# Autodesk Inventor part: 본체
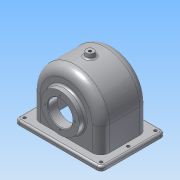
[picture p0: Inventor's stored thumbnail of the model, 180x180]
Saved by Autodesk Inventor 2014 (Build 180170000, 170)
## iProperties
Created: 2015-09
Part Number: 본체
Material: 알루미늄 6061
Document SubType Name: Modeling
Designer: 29
Density: 2.71 g/cm^3
Appearance: 알루미늄 - 평지
Mass: 670.407 g
Surface Area: 886.079 cm^2
Volume: 247.383 cm^3
Author: 29
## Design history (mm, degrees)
sketch "스케치1"
  geometry: L1 (-56, 0)-(-56, -40); L2 (-56, -40)-(56, -40); L3 (56, 0)-(56, -40); A1 r 56 centre (0, 0) between (56, 0) and (-56, 0); 2 further points
  constraints: 6 end point, 2 perpendicular, 2 point on circle, 2 tangent, 1 centre point, 1 coincident, 1 midpoint, 1 vertical, 1 vertical alignment
  dimensions: "d47" = 40 distance from line of L2 point (0, 0); "d48" = 56 radius of A1
extrude "돌출1" new body sketch "스케치1" stored distance "d4" = 77; taper "d5" = 0 deg
feature "쉘4" dims "d50" = 5
sketch "스케치14"
  geometry: L1 (-14, -90.5)-(126, -90.5); L2 (126, -90.5)-(126, 13.5); L3 (126, 13.5)-(-14, 13.5); L4 (-14, 13.5)-(-14, -90.5); L5 (-14, -90.5)-(126, 13.5); L6 (126, -90.5)-(-14, 13.5); 1 further point
  constraints: 12 end point, 2 midpoint, 2 parallel, 1 horizontal, 1 perpendicular
  dimensions: "d51" = 140 distance of L2.end L3.end; "d52" = 104 distance of L3.end L1.start
extrude "돌출10" join sketch "스케치14" distance "d53" = 7; taper "d54" = 0 deg
sketch "스케치15"
  geometry: L1 (5, -72)-(5, -5) reference; L2 (5, -5)-(107, -5) reference; L3 (107, -72)-(5, -72) reference; L4 (107, -5)-(107, -72) reference; 1 further point
extrude "돌출11" cut sketch "스케치15" stored distance "d55" = 7; taper "d56" = 0 deg
sketch "스케치18"
  geometry: L1 (-6, -5.5)-(118, -5.5); L2 (118, -5.5)-(118, 82.5); L3 (118, 82.5)-(-6, 82.5); L4 (-6, 82.5)-(-6, -5.5); L5 (-6, -5.5)-(118, 82.5); L6 (118, -5.5)-(-6, 82.5); C1 r 2.5 at (-6, 82.5); C2 r 2.5 at (-6, 38.5); C3 r 2.5 at (-6, -5.5); 1 further point
  constraints: 12 end point, 3 centre point, 3 midpoint, 2 coincident, 2 parallel, 1 horizontal, 1 perpendicular
  dimensions: "d66" = 124 distance of L2.end L3.end; "d67" = 88 distance of L3.end L1.start; "d68" = 5 diameter of C1; "d69" = 5 diameter of C2; "d70" = 5 diameter of C3
extrude "돌출14" cut sketch "스케치18" stored distance "d71" = 7; taper "d72" = 0 deg
sketch "스케치19"
  geometry: C1 r 31 at (0, 0); A1 r 56 centre (0, 0) between (56, 0) and (-56, 0) reference
  constraints: 1 centre point, 1 coincident
  dimensions: "d73" = 62 diameter of C1
extrude "돌출15" join sketch "스케치19" distance "d74" = 10; taper "d75" = 0 deg
fillet "모깎기2" dims "d76" = 14
fillet "모깎기3" dims "d77" = 9
sketch "스케치20"
  geometry: C1 r 31 at (0, 0) reference; C2 r 20 at (0, 0)
  constraints: 1 centre point, 1 coincident
  dimensions: "d79" = 40 diameter of C2
extrude "돌출16" cut sketch "스케치20" stored distance "d80" = 7; taper "d81" = 0 deg
fillet "모깎기5" dims "d86" = 7
fillet "모깎기6" dims "d87" = 3
node "작업 평면4"
sketch "스케치23"
  geometry: C1 r 28 at (0, 0); 1 further point
  constraints: 1 centre point, 1 coincident
  dimensions: "d92" = 56 diameter of C1
extrude "돌출19" join sketch "스케치23" stored distance "d93" = 16; taper "d94" = 40 deg
sketch "스케치24"
  geometry: C1 r 20 at (0, 0); 1 further point
  constraints: 1 centre point, 1 coincident
  dimensions: "d95" = 40 diameter of C1
extrude "돌출20" cut sketch "스케치24" distance "d96" = 16; taper "d97" = 0 deg
sketch "스케치26" dims "d106" = 48
  geometry: L1 (0, 0)-(0, 24); C1 r 31 at (0, 0) reference
  constraints: 2 end point, 1 coincident, 1 vertical, 1 vertical alignment, 2 other
hole "구멍3" sketch "스케치26" at (0, 24) diameter "d107" = 2.459; stored, may be unused: countersink angle "d111" = 90 deg, drill point angle "d113" = 118 deg; dims "d108" = 6, "d109" = 4, "d110" = 2, "d112" = 8
chamfer "모따기1" distance "d117" = 1; stored, may be unused: second distance "d118" = 2, angle "d119" = 45 deg
sketch "스케치27"
  geometry: L1 (69.5, -7)-(-20.5, -7) reference; L2 (-14, 40)-(-14, 0) reference; 2 further points
  constraints: 1 other
  dimensions: "d120" = 30 distance from line of point (24.5, 23) L1; "d121" = 38.5 distance from line of point (24.5, 23) L2
feature "엠보싱1" sketch "스케치27" dims "d122" = 0.5, "d123" = 0
sketch "스케치28"
  geometry: L1 (28, 19.5)-(39.747, 33.5) reference; L2 (-28, 19.5)-(-39.747, 33.5) reference; L3 (33, 35.5)-(0, 35.5); L4 (0, 38.5)-(42, 38.5) reference; L5 (37.416, 38.5)-(0, 38.5); L6 (0, 38.5)-(0, 35.5); L7 (33.883, 34.29)-(37.416, 38.5); L8 (33, 35.5)-(33, 34.611); A1 r 0.5 centre (33.5, 34.611) between (33, 34.611) and (33.883, 34.29); 2 further points
  constraints: 10 end point, 3 point on line, 2 parallel, 2 point on circle, 2 tangent, 1 centre point, 1 horizontal, 1 perpendicular
  dimensions: "d135" = 3 distance of L4.start L3.end; "d136" = 5 distance between parallel lines of L1 L7; "d137" = 33 horizontal distance of L3.end point (33, 33.237); "d154" = 0.5 radius of A1
revolve "회전1" sketch "스케치28" stored, may be unused: angle "d138" = 90 deg
fillet "모깎기7" dims "d139" = 3
sketch "스케치29" dims "d140" = 56
  geometry: L1 (0, 0)-(0, 28); C1 r 33 at (0, 0) reference
  constraints: 2 end point, 1 coincident, 1 vertical, 1 vertical alignment, 2 other
hole "구멍4" sketch "스케치29" at (0, 28) diameter "d141" = 2.459; stored, may be unused: countersink angle "d145" = 90 deg, drill point angle "d147" = 118 deg; dims "d142" = 7, "d143" = 4, "d144" = 2, "d146" = 9
chamfer "모따기2" distance "d151" = 1; stored, may be unused: second distance "d152" = 2, angle "d153" = 45 deg
fillet "모깎기8" dims "d155" = 3
node "작업 평면5"
sketch "스케치30"
  geometry: C1 r 6 at (-56, -38.5); 1 further point
  constraints: 1 centre point, 1 coincident
  dimensions: "d158" = 12 diameter of C1
extrude "돌출21" join sketch "스케치30" stored distance "d159" = 6; taper "d160" = 10 deg
hole "구멍5" diameter "d163" = 4.459; stored, may be unused: countersink angle "d167" = 90 deg, drill point angle "d169" = 118 deg; dims "d161" = 10, "d162" = 10, "d164" = 30, "d165" = 4, "d166" = 2, "d168" = 9
fillet "모깎기10" dims "d170" = 3
node "솔리드1"
mirror "대칭1"
pattern_circular "원형 패턴2" dims angle "d115" = 360 deg
pattern_circular "원형 패턴3" dims angle "d149" = 360 deg
other parameters: "d0" = 102, "d46" = 114, "d91" = -19
